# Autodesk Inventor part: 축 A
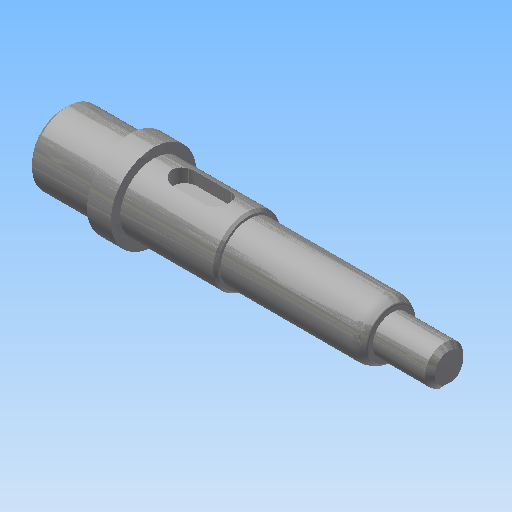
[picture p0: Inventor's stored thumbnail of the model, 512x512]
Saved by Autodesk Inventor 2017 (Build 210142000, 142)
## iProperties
Created: 2020-04
Part Number: 축 A
Material: 강철, 연강
Document SubType Name: Modeling
Designer: mduedu
Density: 7.86 g/cm^3
Appearance: 강철
Mass: 83.1664 g
Surface Area: 37.6212 cm^2
Volume: 10.581 cm^3
Author: mduedu
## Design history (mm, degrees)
sketch "스케치1"
  geometry: L1 (0, 0)-(14, 0); L2 (14, 0)-(14, 7.5); L3 (14, 7.5)-(0, 7.5); L4 (0, 7.5)-(0, 0); L5 (14, 0)-(19, 0); L6 (19, 0)-(19, 9); L7 (19, 9)-(14, 9); L8 (14, 9)-(14, 0); L9 (19, 0)-(39, 0); L10 (39, 0)-(39, 7); L11 (39, 7)-(19, 7); L12 (19, 7)-(19, 0); L13 (39, 0)-(69, 0); L14 (69, 0)-(69, 6); L15 (69, 6)-(39, 6); L16 (39, 6)-(39, 0); L17 (69, 0)-(81, 0); L18 (81, 0)-(81, 4); L19 (81, 4)-(69, 4); L20 (69, 4)-(69, 0)
  constraints: 40 end point, 10 parallel, 5 horizontal, 5 perpendicular
  dimensions: "d0" = 81 distance between parallel lines of L18 L4; "d2" = 14 distance of L2.end L3.end; "d3" = 5 distance of L6.end L7.end; "d4" = 12 distance of L18.end L19.end; "d5" = 8 diameter of L19 L17; "d6" = 12 diameter of L15 L13; "d7" = 14 diameter of L11 L9; "d8" = 15 diameter of L3 L1; "d9" = 18 diameter of L7 L5; "d10" = 42 distance between parallel lines of L10 L18
revolve "회전1" sketch "스케치1" stored, may be unused: angle "d11" = 90 deg
sketch "스케치2"
  geometry: L1 (0, -7.5)-(0, 7.5) reference; L2 (0, 7.5)-(14, 7.5) reference; L3 (14, 7.5)-(14, 9) reference; L4 (14, 9)-(19, 9) reference; L5 (19, 9)-(19, 7) reference; L6 (19, 7)-(39, 7) reference; L7 (39, 7)-(39, 6) reference; L8 (39, 6)-(69, 6) reference; L9 (69, 6)-(69, 4) reference; L10 (69, 4)-(81, 4) reference; L11 (81, 4)-(81, -4) reference; L12 (81, -4)-(69, -4) reference; L13 (69, -4)-(69, -6) reference; L14 (69, -6)-(39, -6) reference; L15 (39, -6)-(39, -7) reference; L16 (39, -7)-(19, -7) reference; L17 (19, -7)-(19, -9) reference; L18 (19, -9)-(14, -9) reference; L19 (14, -9)-(14, -7.5) reference; L20 (14, -7.5)-(0, -7.5) reference; L21 (81, -4)-(73, -4); L22 (73, -4)-(73, -2.8); L23 (73, -2.8)-(81, -2.8); L24 (81, -2.8)-(81, -4); 1 further point
  constraints: 8 end point, 2 parallel, 1 horizontal, 1 perpendicular
  dimensions: "d12" = 8 distance of L22.end L23.end; "d13" = 1.2 distance of L21.end L22.end
extrude "돌출1" cut sketch "스케치2" stored distance "d14" = 2; taper "d15" = 0 deg
fillet "모깎기1" dims "d16" = 1
sketch "스케치3"
  geometry: L1 (0, -7.5)-(0, 7.5) reference; L2 (0, 7.5)-(14, 7.5) reference; L3 (14, 7.5)-(14, 9) reference; L4 (14, 9)-(19, 9) reference; L5 (19, 9)-(19, 7) reference; L6 (19, 7)-(39, 7) reference; L7 (39, 7)-(39, 6) reference; L8 (39, 6)-(69, 6) reference; L9 (69, 6)-(69, 4) reference; L10 (69, 4)-(81, 4) reference; L11 (81, 4)-(81, -2.8) reference; L12 (81, -2.8)-(73, -2.8) reference; L13 (73, -2.8)-(73, -4) reference; L14 (73, -4)-(69, -4) reference; L15 (69, -4)-(69, -6) reference; L16 (69, -6)-(39, -6) reference; L17 (39, -6)-(39, -7) reference; L18 (39, -7)-(19, -7) reference; L19 (19, -7)-(19, -9) reference; L20 (19, -9)-(14, -9) reference; L21 (14, -9)-(14, -7.5) reference; L22 (14, -7.5)-(0, -7.5) reference; L23 (23, 7)-(35, 7); L24 (35, 7)-(35, 4); L25 (35, 4)-(23, 4); L26 (23, 4)-(23, 7); 1 further point
  constraints: 8 end point, 2 parallel, 1 horizontal, 1 perpendicular, 1 point on line
  dimensions: "d17" = 12 distance of L24.end L25.end; "d18" = 3 distance of L23.end L24.end; "d19" = 4 distance from line of L26 L4.end
extrude "돌출2" cut sketch "스케치3" stored distance "d20" = 5; taper "d21" = 0 deg
fillet "모깎기2" dims "d22" = 2.5
chamfer "모따기1" distance "d23" = 1; stored, may be unused: second distance "d24" = 2, angle "d25" = 45 deg
chamfer "모따기2" distance "d26" = 0.5; stored, may be unused: second distance "d27" = 2, angle "d28" = 45 deg
fillet "모깎기3" dims "d29" = 0.3
chamfer "모따기3" distance "d30" = 1.56; stored, may be unused: second distance "d31" = 2, angle "d32" = 30 deg
fillet "모깎기4" dims "d33" = 4, "d34" = 0.5
node "솔리드1"
node "절단 모서리 투영1"
node "절단 모서리 투영2"
